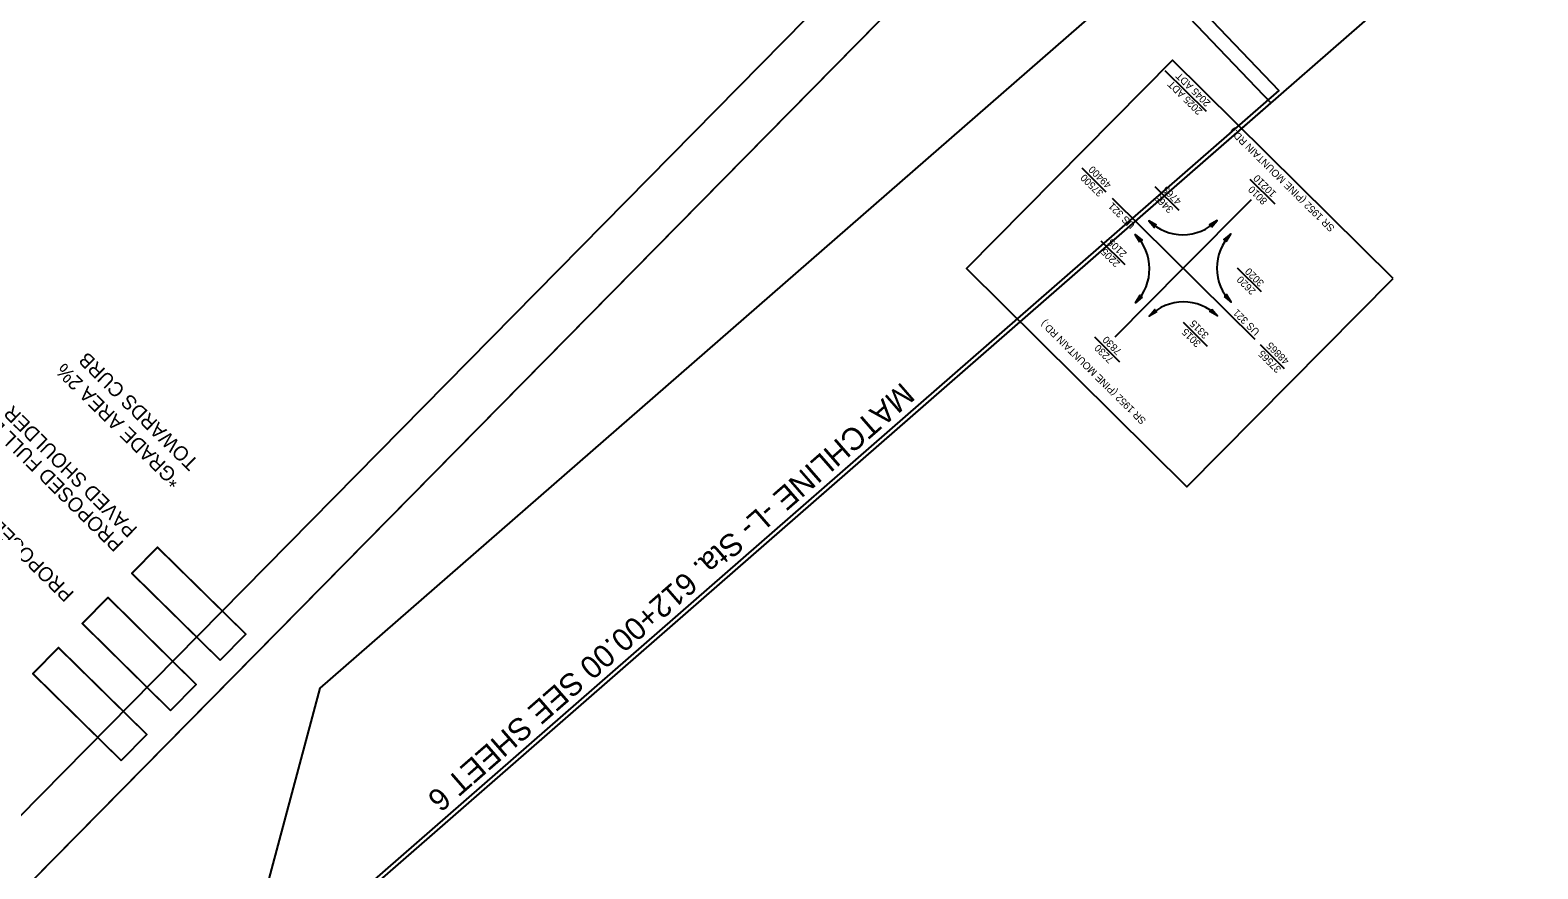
# Model space of a CAD drawing. Extents: x 1265903 to 1267873, y 771347 to 773361.
# Drawn here: x 1266256 to 1266888, y 772486 to 772837 of the extents above; entities that cross this region are included whole.
import ezdxf

# ---------------------------------------------------------------- set-up
doc = ezdxf.new("R2010")
doc.units = 0
for name, color, linetype in [('COGO Default Chain', 7, 'Continuous'), ('Exist DTM Crownline', 7, 'Continuous'), ('Exist Roads EOT', 7, 'Continuous'), ('Exist Utilities Other Pole CELL', 7, 'Continuous'), ('Exist Utilities Other Pole Cogo Number', 7, 'Continuous'), ('Exist Utilities Power Pole Cogo Elevation', 7, 'Continuous'), ('Exist Utilities Power UG Cable SUE LOS B Cogo Number', 7, 'Continuous'), ('Exist Utilities Sanitary Sewer Manhole Cogo Elevation', 7, 'Continuous'), ('Exist Utilities Water Meter CELL', 7, 'Continuous'), ('Prop Conc 1ft 6in Curb and Gutter', 7, 'Continuous'), ('Prop Conc 4in Sidewalk', 7, 'Continuous'), ('Prop Horizontal Alignment Direction Label', 7, 'Continuous'), ('Prop Plan Preparation Crest', 7, 'Continuous'), ('Prop Plan Preparation Watershed Post Construction', 7, 'Continuous'), ('Typical Terminator CELL', 7, 'Continuous')]:
    doc.layers.add(name, color=color, linetype=linetype)

msp = doc.modelspace()

# ---------------------------------------------------------------- linework, layer by layer
at = {"layer": 'COGO Default Chain'}
msp.add_line((1266631.41, 772680.3), (1266387.5, 772467.54), dxfattribs=at)
at = {"layer": 'Exist DTM Crownline'}
msp.add_lwpolyline([(1266335.99, 772573.05), (1266346.73, 772583.95), (1266309.85, 772620.29), (1266299.11, 772609.39)], close=True, dxfattribs=at)
at = {"layer": 'Exist Utilities Other Pole CELL'}
for points in [[(1266757.46, 772748.34), (1266759.33, 772751.53), (1266756.47, 772749.15), (1266757.27, 772749.09)], [(1266728.36, 772718.95), (1266725.19, 772717.05), (1266727.55, 772719.93), (1266727.62, 772719.13)]]:
    msp.add_lwpolyline(points, close=True, dxfattribs=at)
at = {"layer": 'Exist Utilities Other Pole Cogo Number'}
msp.add_lwpolyline([(1266827.36, 772732.86), (1266734.98, 772824.31), (1266648.58, 772737.03), (1266740.96, 772645.58)], close=True, dxfattribs=at)
at = {"layer": 'Exist Utilities Power Pole Cogo Elevation'}
for points in [[(1266816.88, 771715.95), (1267567.86, 772478.14), (1266964.28, 773072.85), (1266841.38, 772965.65), (1266723.84, 773082.29), (1266663.94, 773007.35), (1266766.42, 772900.26), (1266377.83, 772561.31), (1266290.43, 772234.67)], [(1266829.94, 771627.35), (1267580.92, 772389.53), (1266977.34, 772984.25), (1266854.43, 772877.05), (1266736.89, 772993.69), (1266677, 772918.75), (1266779.48, 772811.66), (1266390.89, 772472.71), (1266303.49, 772146.07)], [(1266826.55, 771622.19), (1267577.53, 772384.37), (1266973.95, 772979.08), (1266851.04, 772871.88), (1266733.5, 772988.52), (1266673.61, 772913.58), (1266776.09, 772806.49), (1266387.5, 772467.54), (1266300.09, 772140.9)], [(1266826.55, 771622.19), (1267577.53, 772384.37), (1266973.95, 772979.08), (1266851.04, 772871.88), (1266733.5, 772988.52), (1266673.61, 772913.58), (1266776.09, 772806.49), (1266387.5, 772467.54), (1266300.09, 772140.9)]]:
    msp.add_lwpolyline(points, close=True, dxfattribs=at)
at = {"layer": 'Exist Utilities Power UG Cable SUE LOS B Cogo Number'}
msp.add_lwpolyline([(1266840.58, 771636.43), (1267577.53, 772384.37), (1266973.95, 772979.08), (1266387.5, 772467.54), (1266306.04, 772163.12)], close=True, dxfattribs=at)
at = {"layer": 'Exist Utilities Sanitary Sewer Manhole Cogo Elevation'}
msp.add_lwpolyline([(1266294.53, 772530.98), (1266305.27, 772541.87), (1266268.39, 772578.21), (1266257.65, 772567.32)], close=True, dxfattribs=at)
at = {"layer": 'Exist Utilities Water Meter CELL'}
for p, q in [((1266749.14, 772802.84), (1266731.9, 772819.9)), ((1266707.1, 772769.1), (1266697.04, 772779.06)), ((1266777.97, 772763.95), (1266767.46, 772774.35)), ((1266769.5, 772707.33), (1266709.79, 772766.43)), ((1266737.69, 772761.37), (1266727.63, 772771.33)), ((1266767.83, 772765.87), (1266739.39, 772737.14)), ((1266715.14, 772738.59), (1266705.08, 772748.54)), ((1266710.94, 772708.4), (1266739.39, 772737.14)), ((1266772.17, 772727.24), (1266762.11, 772737.19)), ((1266749.61, 772704.46), (1266739.56, 772714.41)), ((1266712.83, 772697.9), (1266702.33, 772708.3)), ((1266771.68, 772705.17), (1266781.73, 772695.21))]:
    msp.add_line(p, q, dxfattribs=at)
for points in [[(1266728.18, 772755.2), (1266724.99, 772757.07), (1266727.37, 772754.22), (1266727.43, 772755.01)], [(1266751.23, 772754.37), (1266753.58, 772757.22), (1266750.38, 772755.32), (1266751.16, 772755.13)], [(1266721.21, 772748.16), (1266719.3, 772751.33), (1266722.18, 772748.98), (1266721.39, 772748.91)], [(1266722.27, 772725.12), (1266719.45, 772722.74), (1266721.31, 772725.95), (1266721.51, 772725.18)], [(1266756.61, 772725.28), (1266759.47, 772722.94), (1266757.56, 772726.13), (1266757.38, 772725.36)], [(1266751.41, 772720.03), (1266753.78, 772717.2), (1266750.57, 772719.07), (1266751.34, 772719.26)]]:
    msp.add_lwpolyline(points, close=True, dxfattribs=at)
for centre, start, end in [((1266739.21, 772771.44), 225.28869, 315.28869), ((1266705.08, 772736.96), 315.28869, 45.28869), ((1266773.69, 772737.31), 135.28869, 225.28869), ((1266739.56, 772702.83), 45.28869, 135.28869)]:
    msp.add_arc(centre, 20.21, start, end, dxfattribs=at)
at = {"layer": 'Prop Conc 1ft 6in Curb and Gutter'}
for points in [[(1266335.99, 772573.05), (1266346.73, 772583.95), (1266309.76, 772620.38), (1266299.02, 772609.48)], [(1266315.26, 772552.02), (1266326, 772562.91), (1266289.03, 772599.34), (1266278.29, 772588.44)], [(1266294.53, 772530.98), (1266305.27, 772541.87), (1266268.3, 772578.3), (1266257.56, 772567.4)]]:
    msp.add_lwpolyline(points, close=True, dxfattribs=at)
at = {"layer": 'Prop Conc 4in Sidewalk'}
msp.add_line((1267092.63, 773360.64), (1265911.05, 772161.45), dxfattribs=at)
at = {"layer": 'Prop Horizontal Alignment Direction Label'}
msp.add_lwpolyline([(1266315.26, 772552.02), (1266326, 772562.91), (1266289.12, 772599.25), (1266278.38, 772588.35)], close=True, dxfattribs=at)
at = {"layer": 'Prop Plan Preparation Crest'}
msp.add_lwpolyline([(1266043.92, 772264.22), (1266791.85, 771527.31), (1267844.64, 772595.79), (1267247.35, 773184.3), (1267079.43, 773013.88), (1266928.79, 773162.31)], close=True, dxfattribs=at)
at = {"layer": 'Prop Plan Preparation Watershed Post Construction'}
msp.add_lwpolyline([(1266826.95, 771562.93), (1267809.56, 772560.18), (1267212.27, 773148.7), (1267079.43, 773013.88), (1266928.79, 773162.31), (1266079.01, 772299.87)], close=True, dxfattribs=at)
at = {"layer": 'Typical Terminator CELL'}
msp.add_lwpolyline([(1266826.95, 771562.93), (1267809.56, 772560.18), (1267212.27, 773148.7), (1267079.43, 773013.88), (1266928.79, 773162.31), (1266079.01, 772299.87)], close=True, dxfattribs=at)

# ---------------------------------------------------------------- texts
at = {"layer": 'COGO Default Chain'}
msp.add_text('MATCHLINE -L- Sta. 612+00.00 SEE SHEET 6', height=9.375, rotation=221.0811, dxfattribs=at).set_placement((1266621.55, 772689.81))
at = {"layer": 'Exist Roads EOT'}
for s, p in [('PROPOSED 4" CONCRETE SIDEWALK', (1266275.24, 772601.18)), ('*GRADE AREA 2%', (1266320.34, 772649.06)), ('TOWARDS CURB', (1266327.36, 772656.18)), ('PROPOSED FULL DEPTH', (1266295.97, 772622.22)), ('PAVED SHOULDER', (1266301.78, 772628.2))]:
    msp.add_text(s, height=6, rotation=135.42387, dxfattribs=at).set_placement(p)
at = {"layer": 'Exist Utilities Water Meter CELL'}
for s, height, p in [('2045 ADT', 3.032, (1266751.09, 772806.64)), ('2025 ADT', 3.032, (1266747.68, 772803.2)), ('SR 1952 (PINE MOUNTAIN RD.)', 3.0322, (1266803.09, 772754.24)), ('49400', 3.032, (1266709.59, 772772.36)), ('37500', 3.032, (1266706.18, 772768.91)), ('10210', 3.032, (1266778.6, 772768.69)), ('3465', 3.032, (1266735.5, 772762.07)), ('4765', 3.032, (1266738.92, 772765.52)), ('8010', 3.032, (1266774.84, 772765.59)), ('US 321', 3.032, (1266719.46, 772755.42)), ('2105', 3.032, (1266715.97, 772743.49)), ('2205', 3.032, (1266713.17, 772739.44)), ('3020', 3.032, (1266773.51, 772731.27)), ('2620', 3.032, (1266770.07, 772727.85)), ('SR 1952 (PINE MOUNTAIN RD.)', 3.0322, (1266724.06, 772673.62)), ('US 321', 3.032, (1266771.67, 772710.84)), ('3015', 3.032, (1266747.04, 772705.91)), ('3315', 3.032, (1266750.36, 772709.44)), ('7230', 3.032, (1266710.41, 772699.2)), ('7830', 3.032, (1266713.82, 772702.65)), ('48865', 3.032, (1266784.09, 772698.61)), ('37565', 3.032, (1266780.68, 772695.17))]:
    msp.add_text(s, height=height, rotation=135.28869, dxfattribs=at).set_placement(p)

doc.saveas('drawing.dxf')
